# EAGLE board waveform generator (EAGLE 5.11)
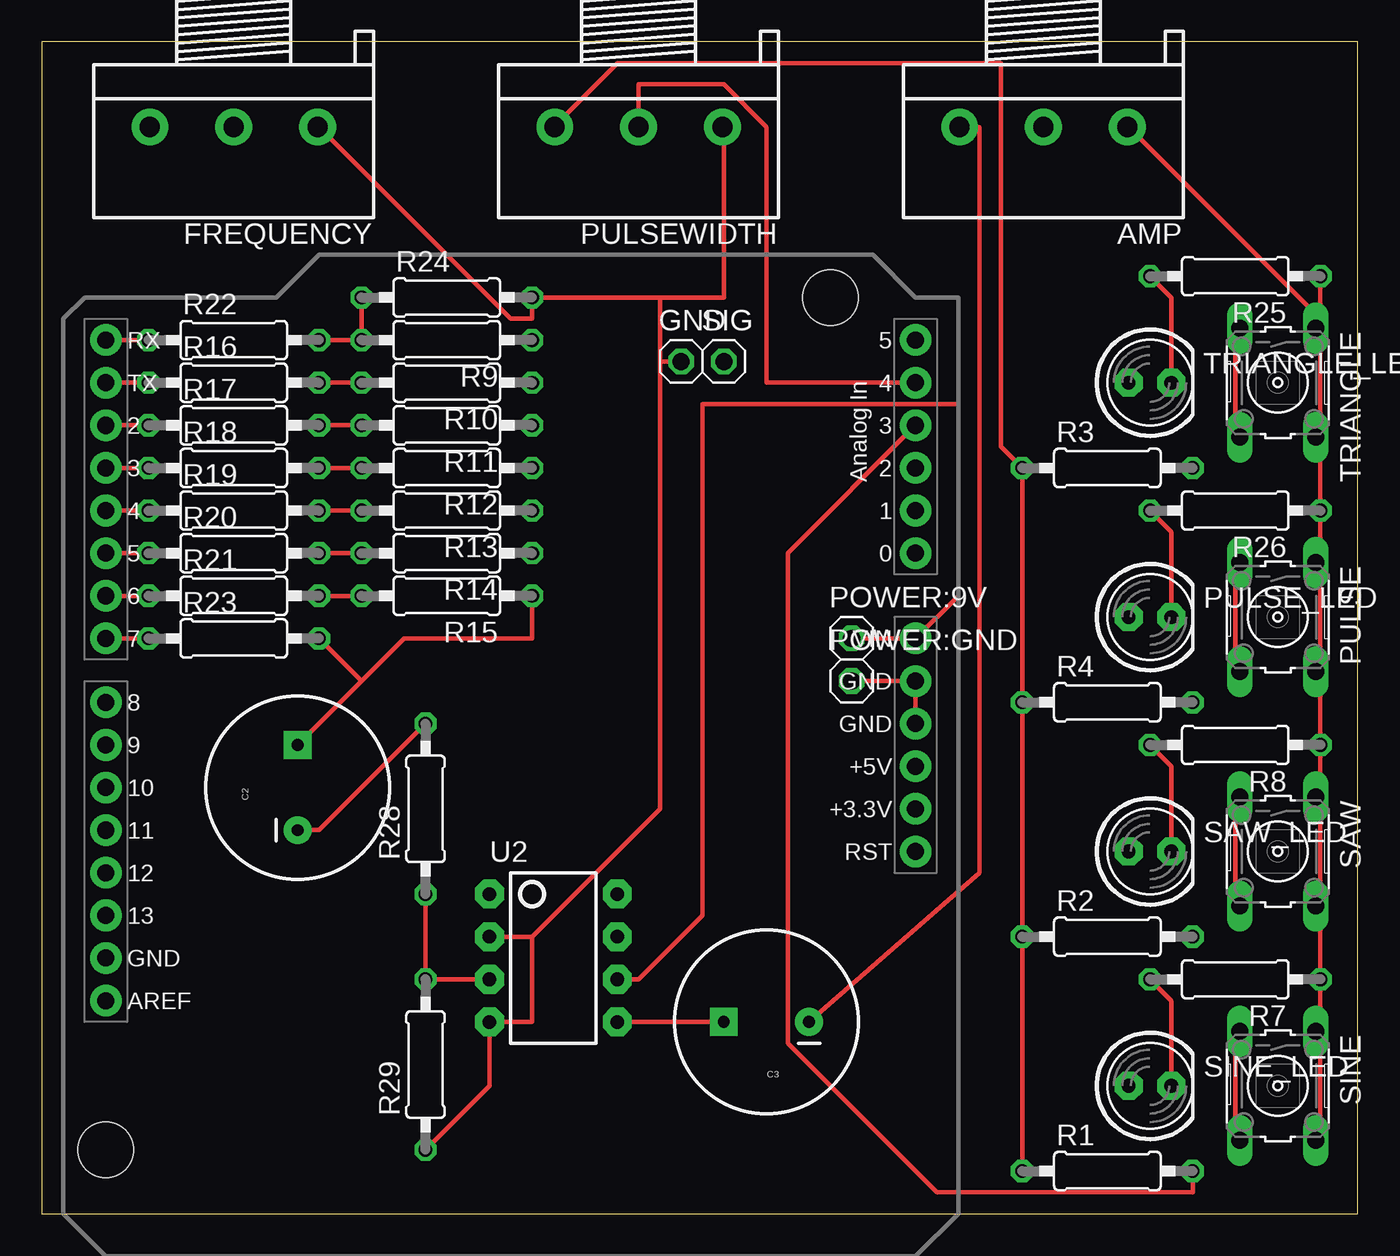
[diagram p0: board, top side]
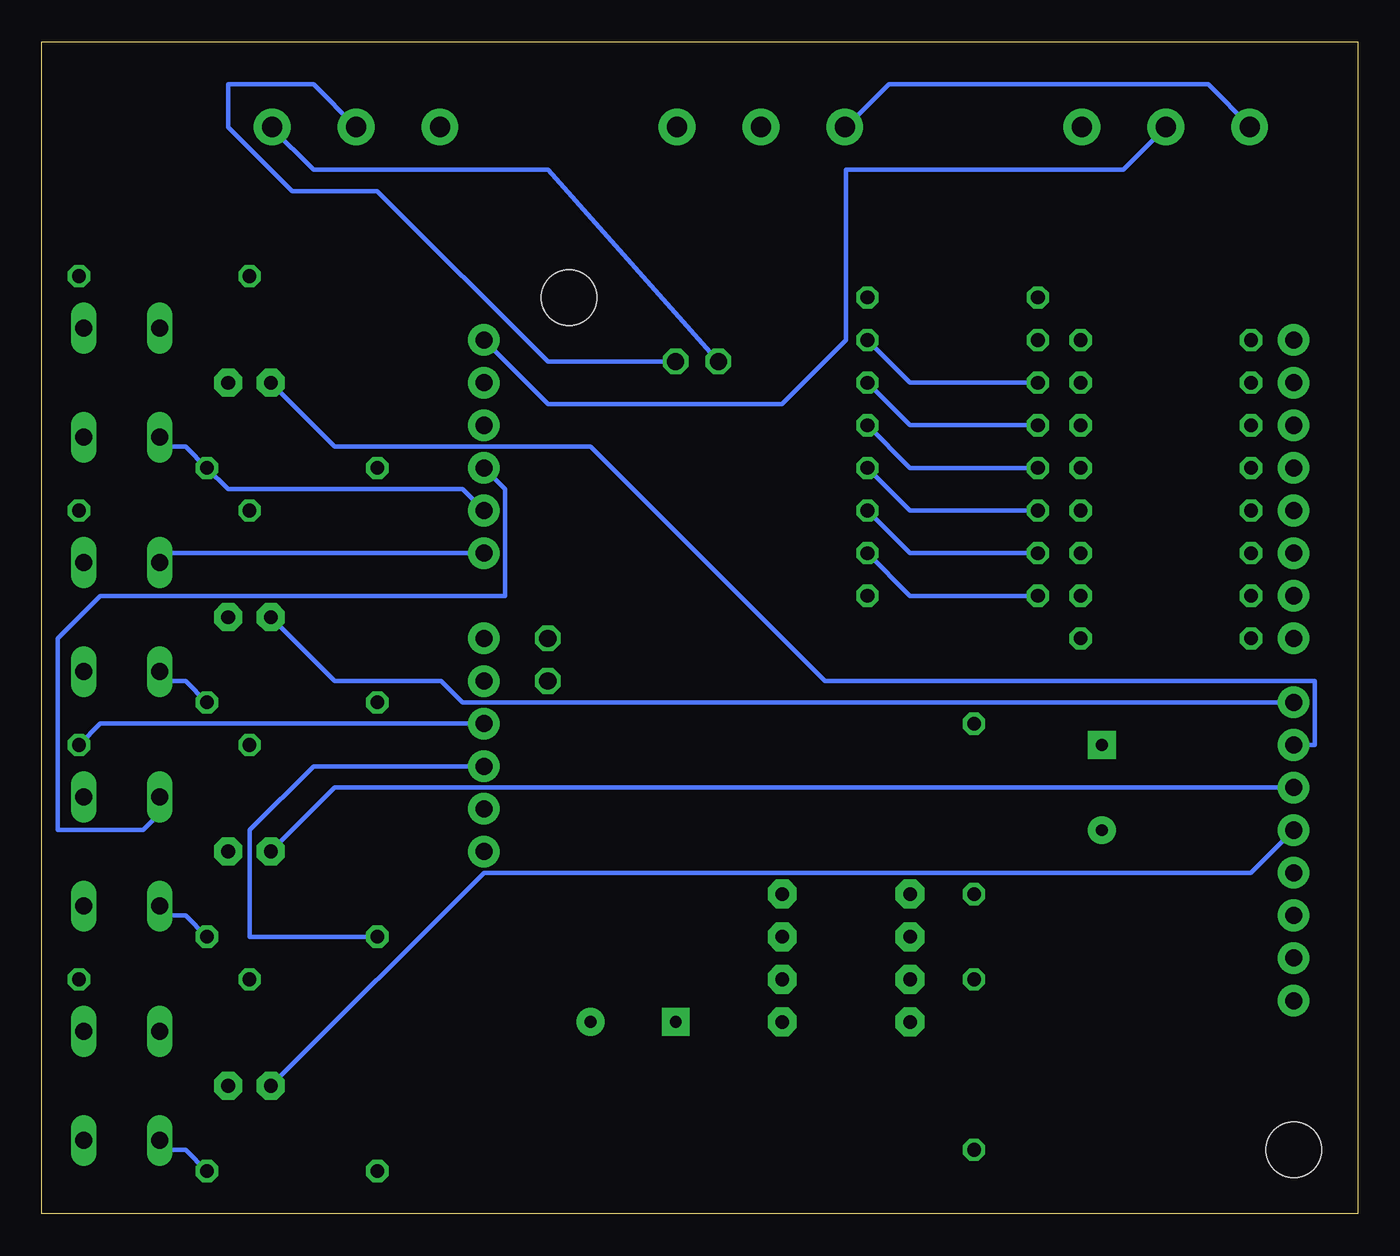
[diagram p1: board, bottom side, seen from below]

Size 78.41 x 69.84 mm. Coordinates in mm from the lower left corner, seen from the top.
Outline: 0,0 78.41,0 78.41,69.84 0,69.84 0,0
Copper layers (1*16): Top 0.035mm / dielectric 1.5mm / Bottom 0.035mm
Design rules "default": minimum track width 10mil, minimum drill 24mil, track to track 8mil, track to pad 8mil, pad to pad 8mil, via to via 8mil, smd to smd 8mil, copper to edge 40mil, drill to drill 8mil, minimum pad ring 10mil, minimum via ring 8mil, stop-mask expansion 4mil, vias tented up to drill 0mil, thermal gap 10mil

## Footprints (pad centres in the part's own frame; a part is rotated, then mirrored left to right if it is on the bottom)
3RP/1610N = drill 1.2 pad 2.184 round: 1 -5,0; 2 0,0; 3 5,0
CPOL-RADIAL-1000UF-25V = drill 0.7 pad 1.651 square: 1 2.54,0 | drill 0.7 pad 1.651 round: 2 -2.54,0
1X01 = drill 1.016 octagon: 1 0,0
B3F-10XX = drill 1.016 long: 1 -3.251,2.261; 2 3.251,2.261; 3 -3.251,-2.261; 4 3.251,-2.261
LED5MM = drill 0.813 pad 1.676 octagon: A -1.27,0; K 1.27,0
0207/10 = drill 0.813 octagon: 1 -5.08,0; 2 5.08,0
DUEMILANOVE_SHIELD = drill 1.016 pad 1.88 round: 3.3V 50.8,26.67; 5V 50.8,29.21; A0 50.8,41.91; A1 50.8,44.45; A2 50.8,46.99; A3 50.8,49.53; A4 50.8,52.07; A5 50.8,54.61; AREF 2.54,15.24; D2 2.54,49.53; D3 2.54,46.99; D4 2.54,44.45; D5 2.54,41.91; D6 2.54,39.37; D7 2.54,36.83; D8 2.54,33.02; D9 2.54,30.48; D10 2.54,27.94; D11 2.54,25.4; D12 2.54,22.86; D13 2.54,20.32; GND@0 50.8,31.75; GND@1 50.8,34.29; GND@2 2.54,17.78; RES 50.8,24.13; RX 2.54,54.61; TX 2.54,52.07; VIN 50.8,36.83 | hole 3.302: 45.72,57.15; 2.54,6.35
DIP08 = drill 0.813 pad 1.727 octagon: 1 -3.81,-3.81; 2 -1.27,-3.81; 3 1.27,-3.81; 4 3.81,-3.81; 5 3.81,3.81; 6 1.27,3.81; 7 -1.27,3.81; 8 -3.81,3.81

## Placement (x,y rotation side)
AMP  [3RP/1610N]  59.69,64.77 180 top
C2  220uF  [CPOL-RADIAL-1000UF-25V]  15.24,25.4 90 top
C3  220uF  [CPOL-RADIAL-1000UF-25V]  43.18,11.43 180 top
FREQUENCY  [3RP/1610N]  11.43,64.77 180 top
GND  [1X01]  38.1,50.8 0 top
POWER:9V  [1X01]  48.26,34.29 0 top
POWER:GND  [1X01]  48.26,31.75 0 top
PULSE  [B3F-10XX]  73.66,35.56 270 top
PULSE_LED  [LED5MM]  66.04,35.56 0 top
PULSEWIDTH  [3RP/1610N]  35.56,64.77 180 top
R1  10k  [0207/10]  63.5,2.54 0 top
R2  10k  [0207/10]  63.5,16.51 0 top
R3  10k  [0207/10]  63.5,44.45 0 top
R4  10k  [0207/10]  63.5,30.48 0 top
R7  220  [0207/10]  71.12,13.97 180 top
R8  220  [0207/10]  71.12,27.94 180 top
R9  10k  [0207/10]  24.13,52.07 180 top
R10  10k  [0207/10]  24.13,49.53 180 top
R11  10k  [0207/10]  24.13,46.99 180 top
R12  10k  [0207/10]  24.13,44.45 180 top
R13  10k  [0207/10]  24.13,41.91 180 top
R14  10k  [0207/10]  24.13,39.37 180 top
R15  10k  [0207/10]  24.13,36.83 180 top
R16  20k  [0207/10]  11.43,49.53 0 top
R17  20k  [0207/10]  11.43,46.99 0 top
R18  20k  [0207/10]  11.43,44.45 0 top
R19  20k  [0207/10]  11.43,41.91 0 top
R20  20k  [0207/10]  11.43,39.37 0 top
R21  20k  [0207/10]  11.43,36.83 0 top
R22  20k  [0207/10]  11.43,52.07 0 top
R23  20k  [0207/10]  11.43,34.29 0 top
R24  20k  [0207/10]  24.13,54.61 0 top
R25  220  [0207/10]  71.12,55.88 180 top
R26  220  [0207/10]  71.12,41.91 180 top
R28  20k  [0207/10]  22.86,24.13 90 top
R29  2.2k  [0207/10]  22.86,8.89 90 top
SAW  [B3F-10XX]  73.66,21.59 270 top
SAW_LED  [LED5MM]  66.04,21.59 0 top
SIG  [1X01]  40.64,50.8 0 top
SINE  [B3F-10XX]  73.66,7.62 270 top
SINE_LED  [LED5MM]  66.04,7.62 0 top
TRIANGLE  [B3F-10XX]  73.66,49.53 270 top
TRIANGLE_LED  [LED5MM]  66.04,49.53 0 top
U1  ARDUINO_SHIELDLABEL  [DUEMILANOVE_SHIELD]  1.27,-2.54 0 top
U2  LM386  [DIP08]  30.48,15.24 270 top

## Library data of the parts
AMP FREQUENCY PULSEWIDTH = pot
C2 C3 U1 U2 = SparkFun
GND POWER:9V POWER:GND SIG = pinhead
PULSE SAW SINE TRIANGLE = switch-omron; MPN: B3F-1000; OC_FARNELL: 176432; OC_NEWARK: 36M3542
PULSE_LED SAW_LED SINE_LED TRIANGLE_LED = adafruit
R1-R4 R7-R26 R28 R29 = resistor

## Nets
N$1: R7.2 SINE_LED.K
N$2: R2.2 SAW.3 SAW.4 U1.A2
N$3: R1.2 SINE.3 SINE.4 U1.A3
N$4: R8.2 SAW_LED.K
N$5: R25.2 TRIANGLE_LED.K
N$6: PULSE_LED.K R26.2
N$7: C2.1 R15.1 R23.2
N$8: C2.2 R28.2
N$9: R3.2 TRIANGLE.3 TRIANGLE.4 U1.A1
N$10: PULSE.3 PULSE.4 R4.2 U1.A0
N$11: PULSE_LED.A U1.D8
N$12: TRIANGLE_LED.A U1.D9
N$13: SAW_LED.A U1.D10
N$14: FREQUENCY.2 U1.A5
N$15: PULSEWIDTH.2 U1.A4
N$16: FREQUENCY.3 PULSEWIDTH.3 R1.1 R2.1 R3.1 R4.1 U1.5V
N$17: SINE_LED.A U1.D11
N$18: R28.1 R29.2 U2.3
N$21: C3.1 U2.5
N$22: AMP.3 C3.2
N$23: POWER:9V.1 U1.VIN U2.6
N$24: AMP.2 SIG.1
N$25: AMP.1 FREQUENCY.1 GND.1 POWER:GND.1 PULSE.1 PULSE.2 PULSEWIDTH.1 R7.1 R8.1 R24.2 R25.1 R26.1 R29.1 SAW.1 SAW.2 SINE.1 SINE.2 TRIANGLE.1 TRIANGLE.2 U1.GND@0 U1.GND@1 U2.2 U2.4
N$26: R9.1 R10.2 R16.2
N$27: R10.1 R11.2 R17.2
N$28: R11.1 R12.2 R18.2
N$29: R12.1 R13.2 R19.2
N$30: R13.1 R14.2 R20.2
N$31: R14.1 R15.2 R21.2
N$32: R9.2 R22.2 R24.1
N$34: R22.1 U1.RX
N$35: R16.1 U1.TX
N$36: R17.1 U1.D2
N$37: R18.1 U1.D3
N$38: R19.1 U1.D4
N$39: R20.1 U1.D5
N$40: R21.1 U1.D6
N$41: R23.1 U1.D7

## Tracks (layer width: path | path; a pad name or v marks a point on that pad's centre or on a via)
N$1
  Top 0.254: R7.2 67.31,12.7 SINE_LED.K
N$2
  Top 0.254: SAW.3 71.12,24.13 71.12,19.05 SAW.4
  Bottom 0.254: R2.2 69.85,17.78 71.12,17.78 SAW.4 | U1.A2 50.8,43.18 50.8,36.83 74.93,36.83 77.47,34.29 77.47,22.86 72.39,22.86 71.12,24.13 SAW.3
N$3
  Top 0.254: SINE.3 71.12,10.16 71.12,5.08 SINE.4 | U1.A3 44.45,39.37 44.45,10.16 53.34,1.27 68.58,1.27 R1.2
  Bottom 0.254: R1.2 69.85,3.81 71.12,3.81 SINE.4
N$4
  Top 0.254: R8.2 67.31,26.67 SAW_LED.K
N$5
  Top 0.254: R25.2 67.31,54.61 TRIANGLE_LED.K
N$6
  Top 0.254: R26.2 67.31,40.64 PULSE_LED.K
N$7
  Top 0.254: C2.1 19.05,31.75 | 19.05,31.75 21.59,34.29 29.21,34.29 R15.1 | 19.05,31.75 R23.2
N$8
  Top 0.254: R28.2 16.51,22.86 C2.2
N$9
  Top 0.254: TRIANGLE.3 71.12,52.07 71.12,46.99 TRIANGLE.4
  Bottom 0.254: TRIANGLE.4 71.12,45.72 69.85,45.72 R3.2 67.31,43.18 53.34,43.18 U1.A1
N$10
  Top 0.254: PULSE.3 71.12,38.1 71.12,33.02 PULSE.4
  Bottom 0.254: R4.2 69.85,31.75 71.12,31.75 PULSE.4 | U1.A0 71.12,39.37 PULSE.3
N$11
  Bottom 0.254: PULSE_LED.A 60.96,31.75 54.61,31.75 53.34,30.48 U1.D8
N$12
  Bottom 0.254: TRIANGLE_LED.A 60.96,45.72 45.72,45.72 31.75,31.75 2.54,31.75 2.54,27.94 U1.D9
N$13
  Bottom 0.254: SAW_LED.A 60.96,25.4 U1.D10
N$14
  Bottom 0.254: U1.A5 48.26,48.26 34.29,48.26 30.48,52.07 30.48,62.23 13.97,62.23 FREQUENCY.2
N$15
  Top 0.254: U1.A4 43.18,49.53 43.18,64.77 40.64,67.31 35.56,67.31 PULSEWIDTH.2
N$16
  Top 0.254: R1.1 R2.1 R4.1 R3.1 57.15,45.72 57.15,68.58 34.29,68.58 30.48,64.77 PULSEWIDTH.3
  Bottom 0.254: FREQUENCY.3 6.35,64.77 8.89,67.31 27.94,67.31 30.48,64.77 PULSEWIDTH.3 | U1.5V 62.23,26.67 66.04,22.86 66.04,16.51 R2.1
N$17
  Bottom 0.254: SINE_LED.A 52.07,20.32 6.35,20.32 U1.D11
N$18
  Top 0.254: U2.3 R29.2 R28.1
N$21
  Top 0.254: U2.5 C3.1
N$22
  Top 0.254: C3.2 55.88,20.32 55.88,64.77 AMP.3
N$23
  Top 0.254: POWER:9V.1 U1.VIN 54.61,36.83 54.61,48.26 39.37,48.26 39.37,34.29 39.37,17.78 35.56,13.97 U2.6
N$24
  Bottom 0.254: SIG.1 48.26,50.8 58.42,60.96 63.5,60.96 67.31,64.77 67.31,67.31 62.23,67.31 AMP.2
N$25
  Top 0.254: SINE.2 76.2,5.08 76.2,10.16 SINE.1 76.2,11.43 R7.1 76.2,17.78 SAW.2 76.2,19.05 76.2,24.13 SAW.1 76.2,25.4 R8.1 76.2,31.75 PULSE.2 76.2,33.02 76.2,38.1 PULSE.1 76.2,39.37 R26.1 76.2,45.72 TRIANGLE.2 76.2,46.99 76.2,52.07 TRIANGLE.1 | 76.2,53.34 R25.1 | 76.2,53.34 TRIANGLE.1 | R29.1 26.67,7.62 U2.4 29.21,11.43 29.21,16.51 | POWER:GND.1 U1.GND@1 U1.GND@0 | 36.83,54.61 35.56,54.61 R24.2 29.21,53.34 27.94,53.34 16.51,64.77 FREQUENCY.1 | 36.83,54.61 40.64,54.61 40.64,64.77 PULSEWIDTH.1 | 36.83,50.8 36.83,34.29 36.83,27.94 36.83,24.13 29.21,16.51 | 36.83,50.8 36.83,54.61 | 29.21,16.51 U2.2 | 36.83,50.8 GND.1 | 76.2,53.34 64.77,64.77 AMP.1 | 76.2,53.34 TRIANGLE.1
  Bottom 0.254: GND.1 48.26,62.23 62.23,62.23 64.77,64.77 AMP.1 | R8.1 74.93,29.21 U1.GND@0
N$26
  Top 0.254: R16.2 R10.2
  Bottom 0.254: R9.1 26.67,49.53 R10.2
N$27
  Top 0.254: R17.2 R11.2
  Bottom 0.254: R10.1 26.67,46.99 R11.2
N$28
  Top 0.254: R18.2 R12.2
  Bottom 0.254: R11.1 26.67,44.45 R12.2
N$29
  Top 0.254: R19.2 R13.2
  Bottom 0.254: R12.1 26.67,41.91 R13.2
N$30
  Top 0.254: R20.2 R14.2
  Bottom 0.254: R13.1 26.67,39.37 R14.2
N$31
  Top 0.254: R21.2 R15.2
  Bottom 0.254: R14.1 26.67,36.83 R15.2
N$32
  Top 0.254: R22.2 R9.2 R24.1
N$34
  Top 0.254: U1.RX R22.1
N$35
  Top 0.254: U1.TX R16.1
N$36
  Top 0.254: U1.D2 R17.1
N$37
  Top 0.254: U1.D3 R18.1
N$38
  Top 0.254: U1.D4 R19.1
N$39
  Top 0.254: U1.D5 R20.1
N$40
  Top 0.254: U1.D6 R21.1
N$41
  Top 0.254: U1.D7 R23.1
